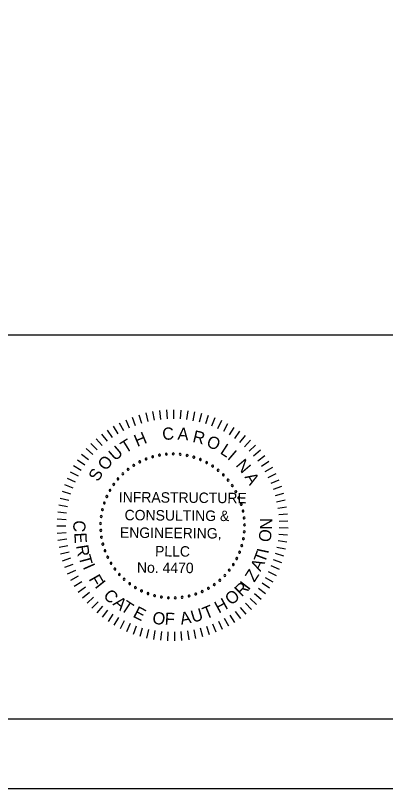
# Model space of a CAD drawing. Extents: x -133.1 to -97, y -1.7 to 20.5.
# Drawn here: x -107.93 to -105.28, y -1.69 to 3.85 of the extents above; entities that cross this region are included whole.
import ezdxf

# ---------------------------------------------------------------- set-up
doc = ezdxf.new("R2010")
doc.units = 0
for name, color, linetype in [('BR_BORDER LINES', 7, 'Continuous'), ('BR_TEXT', 7, 'Continuous'), ('Level 31', 7, 'Continuous')]:
    doc.layers.add(name, color=color, linetype=linetype)

msp = doc.modelspace()

# ---------------------------------------------------------------- linework, layer by layer
at = {"layer": 'BR_BORDER LINES'}
for p, q in [((-110.5071, 1.5591), (-105.1419, 1.5591)), ((-131.3076, -1.191), (-97.6416, -1.191))]:
    msp.add_line(p, q, dxfattribs=at)
at = {"layer": 'BR_TEXT'}
for p, q in [((-107.0007, 0.9998), (-106.9858, 0.9379)), ((-106.9512, 1.01), (-106.9401, 0.9473)), ((-106.9012, 1.0172), (-106.894, 0.9539)), ((-106.8509, 1.0213), (-106.8476, 0.9578)), ((-106.8005, 1.0224), (-106.801, 0.9587)), ((-106.75, 1.0204), (-106.7544, 0.9569)), ((-106.6998, 1.0153), (-106.7081, 0.9522)), ((-106.65, 1.0071), (-106.6621, 0.9446)), ((-107.1439, 0.9513), (-107.1181, 0.8932)), ((-107.0972, 0.9704), (-107.0749, 0.9107)), ((-107.0494, 0.9866), (-107.0308, 0.9257)), ((-106.6007, 0.996), (-106.6166, 0.9343)), ((-106.5523, 0.9818), (-106.5719, 0.9213)), ((-106.5048, 0.9648), (-106.528, 0.9055)), ((-106.4584, 0.9448), (-106.4852, 0.8871)), ((-107.2335, 0.9049), (-107.2008, 0.8503)), ((-107.1895, 0.9295), (-107.1601, 0.873)), ((-106.4133, 0.9221), (-106.4436, 0.8661)), ((-106.3697, 0.8967), (-106.4034, 0.8426)), ((-107.3168, 0.8478), (-107.2776, 0.7976)), ((-107.276, 0.8776), (-107.24, 0.8251)), ((-106.3277, 0.8686), (-106.3646, 0.8167)), ((-106.2875, 0.8381), (-106.3275, 0.7885)), ((-107.3925, 0.7811), (-107.3475, 0.736)), ((-107.3557, 0.8156), (-107.3135, 0.7679)), ((-106.2493, 0.8051), (-106.2922, 0.7581)), ((-107.4272, 0.7444), (-107.3795, 0.7022)), ((-106.2131, 0.7699), (-106.2588, 0.7256)), ((-106.1791, 0.7326), (-106.2275, 0.6911)), ((-107.4895, 0.665), (-107.437, 0.6289)), ((-107.4595, 0.7056), (-107.4094, 0.6664)), ((-106.1475, 0.6932), (-106.1983, 0.6548)), ((-107.5169, 0.6226), (-107.4623, 0.5897)), ((-106.1184, 0.652), (-106.1714, 0.6167)), ((-107.5416, 0.5786), (-107.4852, 0.5491)), ((-106.0918, 0.6091), (-106.1469, 0.5771)), ((-106.0679, 0.5646), (-106.1248, 0.5361)), ((-107.5637, 0.5332), (-107.5055, 0.5072)), ((-106.0467, 0.5188), (-106.1052, 0.4938)), ((-107.5829, 0.4865), (-107.5233, 0.4641)), ((-106.0283, 0.4718), (-106.0883, 0.4504)), ((-107.6126, 0.3901), (-107.5507, 0.3751)), ((-107.5992, 0.4387), (-107.5384, 0.42)), ((-106.0129, 0.4237), (-106.0741, 0.406)), ((-107.623, 0.3407), (-107.5604, 0.3295)), ((-106.0004, 0.3748), (-106.0625, 0.3608)), ((-107.6304, 0.2907), (-107.5672, 0.2834)), ((-105.9909, 0.3252), (-106.0538, 0.3151)), ((-107.6348, 0.2404), (-107.5712, 0.237)), ((-105.9845, 0.2751), (-106.0479, 0.2689)), ((-105.9811, 0.2247), (-106.0448, 0.2224)), ((-107.636, 0.19), (-107.5723, 0.1904)), ((-105.9809, 0.1743), (-106.0445, 0.1758)), ((-107.6342, 0.1395), (-107.5706, 0.1438)), ((-105.9836, 0.1239), (-106.0471, 0.1292)), ((-107.6293, 0.0893), (-107.5661, 0.0974)), ((-105.9895, 0.0737), (-106.0525, 0.0829)), ((-107.6213, 0.0394), (-107.5588, 0.0514)), ((-107.6103, -0.0099), (-107.5487, 0.0059)), ((-105.9984, 0.024), (-106.0607, 0.0371)), ((-107.5964, -0.0584), (-107.5358, -0.0388)), ((-106.0252, -0.0733), (-106.0855, -0.0527)), ((-106.0103, -0.025), (-106.0717, -0.0082)), ((-107.5795, -0.106), (-107.5202, -0.0828)), ((-106.043, -0.1205), (-106.1019, -0.0963)), ((-107.5597, -0.1524), (-107.5019, -0.1256)), ((-106.0636, -0.1666), (-106.1209, -0.1389)), ((-107.5371, -0.1976), (-107.4811, -0.1673)), ((-107.5119, -0.2413), (-107.4578, -0.2077)), ((-106.1131, -0.2545), (-106.1667, -0.22)), ((-106.087, -0.2113), (-106.1426, -0.1802)), ((-107.484, -0.2834), (-107.4321, -0.2465)), ((-106.1418, -0.2961), (-106.1931, -0.2584)), ((-107.4536, -0.3237), (-107.404, -0.2837)), ((-107.4208, -0.362), (-107.3737, -0.3191)), ((-106.2065, -0.3735), (-106.2529, -0.3299)), ((-106.173, -0.3358), (-106.2219, -0.2951)), ((-107.3857, -0.3983), (-107.3413, -0.3527)), ((-107.3485, -0.4324), (-107.307, -0.3841)), ((-106.2423, -0.4092), (-106.2859, -0.3628)), ((-107.3092, -0.4642), (-107.2708, -0.4135)), ((-107.2681, -0.4935), (-107.2328, -0.4405)), ((-106.32, -0.4736), (-106.3576, -0.4222)), ((-106.2801, -0.4426), (-106.3208, -0.3936)), ((-107.2253, -0.5203), (-107.1933, -0.4652)), ((-107.1809, -0.5444), (-107.1523, -0.4875)), ((-106.4498, -0.5513), (-106.4774, -0.4939)), ((-106.4049, -0.528), (-106.436, -0.4725)), ((-106.3616, -0.5021), (-106.3961, -0.4485)), ((-107.1352, -0.5657), (-107.1101, -0.5072)), ((-107.0882, -0.5842), (-107.0668, -0.5243)), ((-107.0402, -0.5998), (-107.0225, -0.5387)), ((-106.9913, -0.6125), (-106.9773, -0.5504)), ((-106.6406, -0.6158), (-106.6536, -0.5535)), ((-106.5915, -0.6041), (-106.6083, -0.5427)), ((-106.5432, -0.5894), (-106.5637, -0.5291)), ((-106.4959, -0.5718), (-106.52, -0.5128)), ((-106.9418, -0.6221), (-106.9316, -0.5593)), ((-106.8918, -0.6288), (-106.8854, -0.5654)), ((-106.8414, -0.6323), (-106.8389, -0.5687)), ((-106.7909, -0.6328), (-106.7923, -0.5691)), ((-106.7405, -0.6302), (-106.7458, -0.5667)), ((-106.6903, -0.6245), (-106.6995, -0.5615))]:
    msp.add_line(p, q, dxfattribs=at)
for centre, start, end in [((-106.9977, 0.6702), 21.6807, 201.6807), ((-106.9977, 0.6702), 201.6807, 21.6807), ((-106.9506, 0.6862), 16.1422, 196.1422), ((-106.9506, 0.6862), 196.1422, 16.1422), ((-106.9021, 0.6977), 10.6038, 190.6038), ((-106.9021, 0.6977), 190.6038, 10.6038), ((-106.8527, 0.7043), 5.0653, 185.0653), ((-106.8527, 0.7043), 185.0653, 5.0653), ((-106.8029, 0.7062), 359.5268, 179.5268), ((-106.8029, 0.7062), 179.5268, 359.5268), ((-106.7531, 0.7033), 173.9884, 353.9884), ((-106.7531, 0.7033), 353.9884, 173.9884), ((-106.7039, 0.6956), 168.4499, 348.4499), ((-106.7039, 0.6956), 348.4499, 168.4499), ((-106.6557, 0.6832), 162.9114, 342.9114), ((-106.6557, 0.6832), 342.9114, 162.9114), ((-106.6088, 0.6662), 157.373, 337.373), ((-106.6088, 0.6662), 337.373, 157.373), ((-107.0864, 0.6248), 32.7576, 212.7576), ((-107.0864, 0.6248), 212.7576, 32.7576), ((-107.0431, 0.6496), 27.2191, 207.2191), ((-107.0431, 0.6496), 207.2191, 27.2191), ((-106.5639, 0.6447), 151.8345, 331.8345), ((-106.5639, 0.6447), 331.8345, 151.8345), ((-106.5212, 0.619), 146.2961, 326.2961), ((-106.5212, 0.619), 326.2961, 146.2961), ((-107.1646, 0.5633), 43.8345, 223.8345), ((-107.1646, 0.5633), 223.8345, 43.8345), ((-107.127, 0.5959), 38.2961, 218.2961), ((-107.127, 0.5959), 218.2961, 38.2961), ((-106.4811, 0.5893), 140.7576, 320.7576), ((-106.4811, 0.5893), 320.7576, 140.7576), ((-106.4442, 0.5559), 135.2191, 315.2191), ((-106.4442, 0.5559), 315.2191, 135.2191), ((-107.1989, 0.5271), 49.373, 229.373), ((-107.1989, 0.5271), 229.373, 49.373), ((-106.4106, 0.5191), 129.6807, 309.6807), ((-106.4106, 0.5191), 309.6807, 129.6807), ((-107.2563, 0.4458), 60.4499, 240.4499), ((-107.2563, 0.4458), 240.4499, 60.4499), ((-107.2296, 0.4879), 54.9114, 234.9114), ((-107.2296, 0.4879), 234.9114, 54.9114), ((-106.3808, 0.4792), 124.1422, 304.1422), ((-106.3808, 0.4792), 304.1422, 124.1422), ((-106.3549, 0.4366), 298.6038, 118.6038), ((-107.2788, 0.4014), 65.9884, 245.9884), ((-107.2788, 0.4014), 245.9884, 65.9884), ((-106.3549, 0.4366), 118.6038, 298.6038), ((-106.3333, 0.3917), 113.0653, 293.0653), ((-106.3333, 0.3917), 293.0653, 113.0653), ((-107.297, 0.3549), 71.5268, 251.5268), ((-107.297, 0.3549), 251.5268, 71.5268), ((-106.3161, 0.3449), 107.5268, 287.5268), ((-106.3161, 0.3449), 287.5268, 107.5268), ((-107.3106, 0.307), 77.0653, 257.0653), ((-107.3106, 0.307), 257.0653, 77.0653), ((-106.3035, 0.2967), 101.9884, 281.9884), ((-106.3035, 0.2967), 281.9884, 101.9884), ((-107.3195, 0.258), 82.6038, 262.6038), ((-107.3195, 0.258), 262.6038, 82.6038), ((-106.2956, 0.2475), 96.4499, 276.4499), ((-106.2956, 0.2475), 276.4499, 96.4499), ((-107.3236, 0.2083), 88.1422, 268.1422), ((-107.3236, 0.2083), 268.1422, 88.1422), ((-106.2925, 0.1977), 90.9114, 270.9114), ((-106.2925, 0.1977), 270.9114, 90.9114), ((-107.3229, 0.1585), 93.6807, 273.6807), ((-107.3174, 0.109), 99.2191, 279.2191), ((-107.3229, 0.1585), 273.6807, 93.6807), ((-107.3174, 0.109), 279.2191, 99.2191), ((-106.2942, 0.1479), 85.373, 265.373), ((-106.2942, 0.1479), 265.373, 85.373), ((-107.3071, 0.0602), 104.7576, 284.7576), ((-107.3071, 0.0602), 284.7576, 104.7576), ((-106.312, 0.05), 74.2961, 254.2961), ((-106.312, 0.05), 254.2961, 74.2961), ((-106.3007, 0.0985), 79.8345, 259.8345), ((-106.3007, 0.0985), 259.8345, 79.8345), ((-107.2922, 0.0126), 110.2961, 290.2961), ((-107.2922, 0.0126), 290.2961, 110.2961), ((-106.3279, 0.0028), 68.7576, 248.7576), ((-106.3279, 0.0028), 248.7576, 68.7576), ((-107.2728, -0.0332), 115.8345, 295.8345), ((-107.2728, -0.0332), 295.8345, 115.8345), ((-106.3483, -0.0427), 63.2191, 243.2191), ((-106.3483, -0.0427), 243.2191, 63.2191), ((-107.249, -0.077), 121.373, 301.373), ((-107.249, -0.077), 301.373, 121.373), ((-106.3729, -0.086), 57.6807, 237.6807), ((-106.3729, -0.086), 237.6807, 57.6807), ((-107.2211, -0.1183), 126.9114, 306.9114), ((-107.2211, -0.1183), 306.9114, 126.9114), ((-107.1894, -0.1567), 132.4499, 312.4499), ((-107.1894, -0.1567), 312.4499, 132.4499), ((-106.4342, -0.1645), 46.6038, 226.6038), ((-106.4342, -0.1645), 226.6038, 46.6038), ((-106.4016, -0.1267), 52.1422, 232.1422), ((-106.4016, -0.1267), 232.1422, 52.1422), ((-107.1541, -0.1919), 137.9884, 317.9884), ((-107.1541, -0.1919), 317.9884, 137.9884), ((-107.1156, -0.2235), 143.5268, 323.5268), ((-107.1156, -0.2235), 323.5268, 143.5268), ((-106.4702, -0.1989), 41.0653, 221.0653), ((-106.4702, -0.1989), 221.0653, 41.0653), ((-107.0742, -0.2512), 149.0653, 329.0653), ((-107.0742, -0.2512), 329.0653, 149.0653), ((-107.0303, -0.2749), 154.6038, 334.6038), ((-107.0303, -0.2749), 334.6038, 154.6038), ((-106.5957, -0.2793), 24.4499, 204.4499), ((-106.5957, -0.2793), 204.4499, 24.4499), ((-106.5513, -0.2566), 29.9884, 209.9884), ((-106.5513, -0.2566), 209.9884, 29.9884), ((-106.5093, -0.2297), 35.5268, 215.5268), ((-106.5093, -0.2297), 215.5268, 35.5268), ((-106.9843, -0.2941), 160.1422, 340.1422), ((-106.9843, -0.2941), 340.1422, 160.1422), ((-106.9367, -0.3089), 165.6807, 345.6807), ((-106.9367, -0.3089), 345.6807, 165.6807), ((-106.8879, -0.3189), 171.2191, 351.2191), ((-106.8879, -0.3189), 351.2191, 171.2191), ((-106.8384, -0.3242), 356.7576, 176.7576), ((-106.8384, -0.3242), 176.7576, 356.7576), ((-106.7885, -0.3248), 2.2961, 182.2961), ((-106.7885, -0.3248), 182.2961, 2.2961), ((-106.7389, -0.3205), 7.8345, 187.8345), ((-106.7389, -0.3205), 187.8345, 7.8345), ((-106.6899, -0.3114), 13.373, 193.373), ((-106.6899, -0.3114), 193.373, 13.373), ((-106.642, -0.2976), 18.9114, 198.9114), ((-106.642, -0.2976), 198.9114, 18.9114)]:
    msp.add_arc(centre, 0.00701, start, end, dxfattribs=at)
at = {"layer": 'Level 31'}
msp.add_lwpolyline([(-133.1409, -1.691), (-97.141, -1.691), (-97.141, 20.309), (-133.1409, 20.309)], close=True, dxfattribs=at)

# ---------------------------------------------------------------- texts
at = {"layer": 'BR_TEXT'}
for s, height, rotation, p in [('C', 0.0872, 4.7281, (-106.8784, 0.8048)), ('A', 0.0872, 355.6981, (-106.7739, 0.8098)), ('H', 0.0872, 22.7882, (-107.0612, 0.7554)), ('R', 0.0872, 346.6681, (-106.6696, 0.7928)), ('O', 0.0872, 337.638, (-106.5719, 0.763)), ('T', 0.0872, 31.8182, (-107.1461, 0.7078)), ('L', 0.0872, 327.108, (-106.4731, 0.7125)), ('U', 0.0872, 40.8482, (-107.2194, 0.6516)), ('I', 0.0872, 319.578, (-106.4205, 0.6747)), ('O', 0.0872, 49.8782, (-107.2864, 0.5806)), ('N', 0.0872, 310.548, (-106.3597, 0.6239)), ('S', 0.0872, 58.9083, (-107.3418, 0.5024)), ('A', 0.0872, 301.5179, (-106.2946, 0.5415)), ('INFRASTRUCTURE', 0.074771, 359.5268, (-107.1932, 0.3599)), ('CONSULTING &', 0.074771, 359.5268, (-107.1519, 0.2313)), ('C', 0.0872, 267.025, (-107.5168, 0.2325)), ('N', 0.0872, 89.2085, (-106.0953, 0.1628)), ('ENGINEERING,', 0.074771, 359.5268, (-107.1855, 0.1059)), ('E', 0.0872, 273.025, (-107.5124, 0.1409)), ('O', 0.0872, 83.2085, (-106.1064, 0.0713)), ('R', 0.0872, 279.025, (-107.4996, 0.0487)), ('PLLC', 0.07477, 359.5268, (-106.9338, -0.0277)), ('T', 0.0872, 69.3954, (-106.1476, -0.0805)), ('I', 0.0872, 77.9093, (-106.1219, -0.013)), ('T', 0.0872, 285.025, (-107.4822, -0.0301)), ('I', 0.0872, 293.7713, (-107.4525, -0.1032)), ('No. 4470', 0.07477, 359.5268, (-107.0633, -0.1446)), ('A', 0.0872, 63.3954, (-106.1784, -0.1408)), ('F', 0.0872, 299.7713, (-107.4113, -0.1893)), ('Z', 0.0872, 57.3954, (-106.2222, -0.2172)), ('I', 0.0872, 308.5268, (-107.3692, -0.2431)), ('R', 0.0872, 44.5268, (-106.3127, -0.3221)), ('I', 0.0872, 52.3339, (-106.2633, -0.2748)), ('C', 0.0872, 314.5268, (-107.3099, -0.3133)), ('O', 0.0872, 38.5268, (-106.3893, -0.3821)), ('A', 0.0872, 320.5268, (-107.2407, -0.3718)), ('H', 0.0872, 28.5268, (-106.4774, -0.4381)), ('T', 0.0872, 326.5268, (-107.1863, -0.4103)), ('E', 0.0872, 332.5268, (-107.0977, -0.4581)), ('T', 0.0872, 22.5268, (-106.5706, -0.4799)), ('O', 0.0872, 350.5268, (-106.9576, -0.507)), ('F', 0.0872, 356.5268, (-106.8661, -0.5161)), ('A', 0.0872, 10.5268, (-106.7462, -0.5177)), ('U', 0.0872, 16.5268, (-106.6623, -0.5042))]:
    msp.add_text(s, height=height, rotation=rotation, dxfattribs=at).set_placement(p)

doc.saveas('drawing.dxf')
